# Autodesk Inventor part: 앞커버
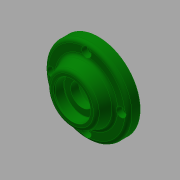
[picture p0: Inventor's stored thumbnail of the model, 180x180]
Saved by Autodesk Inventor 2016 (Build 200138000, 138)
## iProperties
Created: 2017-08
Part Number: 앞커버
Material: 알루미늄 6061
Document SubType Name: Modeling
Designer: mduedu
Density: 1 g/cm^3
Appearance: 진녹색
Author: mduedu
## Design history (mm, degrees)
sketch "스케치1"
  geometry: C1 r 35 at (0, 0); 1 further point
  constraints: 1 centre point, 1 coincident
  dimensions: "d0" = 70 diameter of C1
extrude "돌출1" new body sketch "스케치1" distance "d1" = 10; taper "d2" = 0 deg
sketch "스케치2"
  geometry: C1 r 24 at (0, 0); 1 further point
  constraints: 1 centre point, 1 coincident
  dimensions: "d3" = 48 diameter of C1
node "작업 평면1"
sketch "스케치3"
  geometry: C1 r 20 at (0, 0); 1 further point
  constraints: 1 centre point, 1 coincident
  dimensions: "d5" = 40 diameter of C1
feature "로프트1" sketch "스케치3" dims "d6" = 0, "d7" = 90 deg, "d8" = 0, "d9" = 90 deg
sketch "스케치4"
  geometry: C1 r 24 at (0, 0) reference; 1 further point
extrude "돌출2" join sketch "스케치4" distance "d10" = 8; taper "d11" = 0 deg
hole "구멍1" diameter "d14" = 40; stored, may be unused: countersink angle "d18" = 90 deg, drill point angle "d20" = 0 deg; dims "d12" = 10, "d13" = 10, "d15" = 6, "d16" = 4, "d17" = 2, "d19" = 12
hole "구멍2" diameter "d23" = 34; stored, may be unused: countersink angle "d27" = 90 deg, drill point angle "d29" = 0 deg; dims "d21" = 10, "d22" = 10, "d24" = 6, "d25" = 4, "d26" = 2, "d28" = 3
hole "구멍3" diameter "d32" = 19; stored, may be unused: countersink angle "d36" = 90 deg, drill point angle "d38" = 0 deg; dims "d30" = 10, "d31" = 10, "d33" = 6, "d34" = 4, "d35" = 2, "d37" = 3
chamfer "모따기1" distance "d39" = 1; stored, may be unused: second distance "d40" = 2, angle "d41" = 45 deg
sketch "스케치5"
  geometry: C1 r 15 at (0, 0); 1 further point
  constraints: 1 centre point, 1 coincident
  dimensions: "d42" = 30 diameter of C1
extrude "돌출3" cut sketch "스케치5" distance "d43" = 8.3; taper "d44" = 0 deg
chamfer "모따기2" distance "d47" = 0.8; stored, may be unused: second distance "d48" = 2, angle "d49" = 30 deg
fillet "모깎기1" dims "d50" = 0.3
fillet "모깎기2" dims "d51" = 0.3
fillet "모깎기3" dims "d52" = 3
sketch "스케치6" dims "d53" = 58
  geometry: 6 further points
  constraints: 2 vertical alignment, 1 coincident, 7 other
  dimensions: "d56" = 360 deg dimension on point (0, 0) point (0, 29) (derived)
sketch "스케치9" dims "d85" = 58 (derived)
  geometry: 6 further points
  constraints: 1 coincident, 1 vertical alignment, 6 other
hole "구멍6" sketch "스케치9" at (-29, 0), (0, -29), (29, 0), (0, 29) diameter "d72" = 4.5; stored, may be unused: countersink angle "d76" = 90 deg, drill point angle "d78" = 0 deg; dims "d73" = 6, "d74" = 8, "d75" = 4.6, "d77" = 8
fillet "모깎기4" dims "d79" = 3
fillet "모깎기5" dims "d80" = 3
fillet "모깎기6" dims "d81" = 3
node "솔리드1"
other parameters: "d4" = 12
